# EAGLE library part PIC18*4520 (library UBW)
PIC18*4520 Microchip FLASH Microcontroller with A/D DEVICE FEATURES FeaturePIC18*4520 Program Memory (bytes) 32768 Program Memory (instructions) 16384 Interupt Sources 20 I/O Ports Ports A, B, C, D, E Capture/Compare/PWM Modules 1 Enhanced Capture/Compare/PWM Modules 1 Parallel Communications (PSP) Yes 10-bit Analog-to-Digital Module 13 input Channels Package Types 40-pin PDIP 44-pin TQFP 44-pin QFN NOTES: F only after 18, means standard voltage range from 4.2v to 5.5v LF after 18, means extended voltage range from 2.0v to 5.5v -E before / denotes extended temperature range from -40&deg;C to +120&deg;C -I before / denotes industrial temperature range from -40&deg;C to +85&deg;C /PT suffix denotes TQFP package /SO suffix denotes SOIC package /SP suffix denotes Skinny Plastic DIP package /P suffix denotes Plastic DIP package /ML suffix denotes QFN package
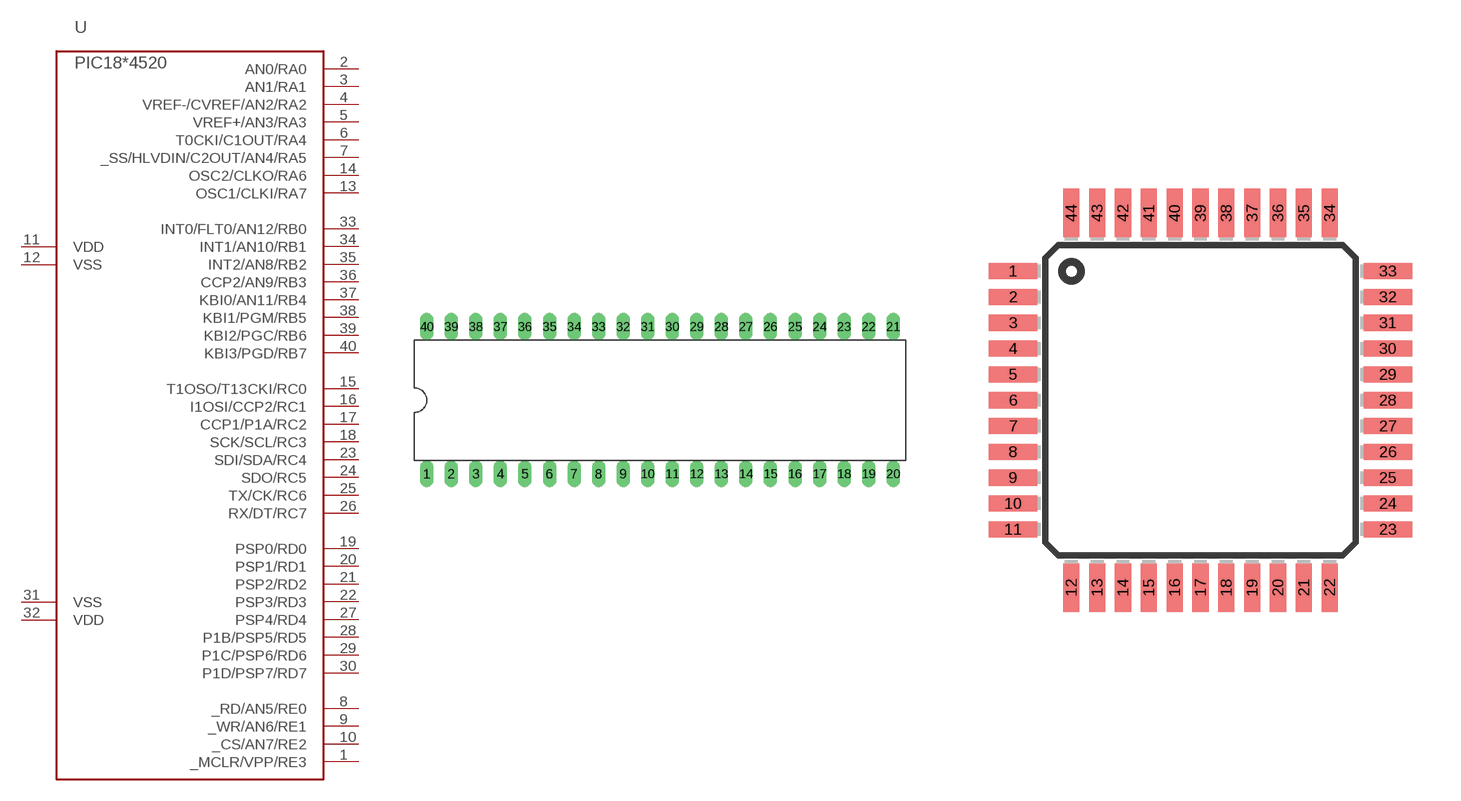
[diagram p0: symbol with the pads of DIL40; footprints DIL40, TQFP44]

Designator prefix -

## PIC18F4520-I/P, PIC18LF4520-I/P  [DIL40]
1  _MCLR/VPP/RE3  in
2  AN0/RA0
3  AN1/RA1
4  VREF-/CVREF/AN2/RA2
5  VREF+/AN3/RA3
6  T0CKI/C1OUT/RA4
7  _SS/HLVDIN/C2OUT/AN4/RA5
8  _RD/AN5/RE0
9  _WR/AN6/RE1
10  _CS/AN7/RE2
11  VDD  pwr
12  VSS  pwr
13  OSC1/CLKI/RA7
14  OSC2/CLKO/RA6
15  T1OSO/T13CKI/RC0
16  I1OSI/CCP2/RC1
17  CCP1/P1A/RC2
18  SCK/SCL/RC3
19  PSP0/RD0
20  PSP1/RD1
21  PSP2/RD2
22  PSP3/RD3
23  SDI/SDA/RC4
24  SDO/RC5
25  TX/CK/RC6
26  RX/DT/RC7
27  PSP4/RD4
28  P1B/PSP5/RD5
29  P1C/PSP6/RD6
30  P1D/PSP7/RD7
31  VSS  pwr
32  VDD  pwr
33  INT0/FLT0/AN12/RB0
34  INT1/AN10/RB1
35  INT2/AN8/RB2
36  CCP2/AN9/RB3
37  KBI0/AN11/RB4
38  KBI1/PGM/RB5
39  KBI2/PGC/RB6
40  KBI3/PGD/RB7

## PIC18F4520-E/P, PIC18LF4520-E/P  [DIL40]
Pads as for DIL40

## PIC18F4520-I/PT, PIC18LF4520-I/PT  [TQFP44]
1  RX/DT/RC7
2  PSP4/RD4
3  P1B/PSP5/RD5
4  P1C/PSP6/RD6
5  P1D/PSP7/RD7
6  VSS  pwr
7  VDD  pwr
8  INT0/FLT0/AN12/RB0
9  INT1/AN10/RB1
10  INT2/AN8/RB2
11  CCP2/AN9/RB3
14  KBI0/AN11/RB4
15  KBI1/PGM/RB5
16  KBI2/PGC/RB6
17  KBI3/PGD/RB7
18  _MCLR/VPP/RE3  in
19  AN0/RA0
20  AN1/RA1
21  VREF-/CVREF/AN2/RA2
22  VREF+/AN3/RA3
23  T0CKI/C1OUT/RA4
24  _SS/HLVDIN/C2OUT/AN4/RA5
25  _RD/AN5/RE0
26  _WR/AN6/RE1
27  _CS/AN7/RE2
28  VDD  pwr
29  VSS  pwr
30  OSC1/CLKI/RA7
31  OSC2/CLKO/RA6
32  T1OSO/T13CKI/RC0
35  I1OSI/CCP2/RC1
36  CCP1/P1A/RC2
37  SCK/SCL/RC3
38  PSP0/RD0
39  PSP1/RD1
40  PSP2/RD2
41  PSP3/RD3
42  SDI/SDA/RC4
43  SDO/RC5
44  TX/CK/RC6

## PIC18F4520-E/PT, PIC18LF4520-E/PT  [TQFP44]
Pads as for TQFP44

## Footprint DIL40 (pad centres in mm)
Dual In Line package type P
drill 0.9 long: 1 -24.13,-7.62; 2 -21.59,-7.62; 3 -19.05,-7.62; 4 -16.51,-7.62; 5 -13.97,-7.62; 6 -11.43,-7.62; 7 -8.89,-7.62; 8 -6.35,-7.62; 9 -3.81,-7.62; 10 -1.27,-7.62; 11 1.27,-7.62; 12 3.81,-7.62; 13 6.35,-7.62; 14 8.89,-7.62; 15 11.43,-7.62; 16 13.97,-7.62; 17 16.51,-7.62; 18 19.05,-7.62; 19 21.59,-7.62; 20 24.13,-7.62; 21 24.13,7.62; 22 21.59,7.62; 23 19.05,7.62; 24 16.51,7.62; 25 13.97,7.62; 26 11.43,7.62; 27 8.89,7.62; 28 6.35,7.62; 29 3.81,7.62; 30 1.27,7.62; 31 -1.27,7.62; 32 -3.81,7.62; 33 -6.35,7.62; 34 -8.89,7.62; 35 -11.43,7.62; 36 -13.97,7.62; 37 -16.51,7.62; 38 -19.05,7.62; 39 -21.59,7.62; 40 -24.13,7.62

## Footprint TQFP44 (pad centres in mm)
Thin Quad Flat Pack package type TQ
smd 1.5 x 0.5: 1 -5.8,4; 2 -5.8,3.2; 3 -5.8,2.4; 4 -5.8,1.6; 5 -5.8,0.8; 6 -5.8,0; 7 -5.8,-0.8; 8 -5.8,-1.6; 9 -5.8,-2.4; 10 -5.8,-3.2; 11 -5.8,-4; 23 5.8,-4; 24 5.8,-3.2; 25 5.8,-2.4; 26 5.8,-1.6; 27 5.8,-0.8; 28 5.8,0; 29 5.8,0.8; 30 5.8,1.6; 31 5.8,2.4; 32 5.8,3.2; 33 5.8,4
smd 0.5 x 1.5: 12 -4,-5.8; 13 -3.2,-5.8; 14 -2.4,-5.8; 15 -1.6,-5.8; 16 -0.8,-5.8; 17 0,-5.8; 18 0.8,-5.8; 19 1.6,-5.8; 20 2.4,-5.8; 21 3.2,-5.8; 22 4,-5.8; 34 4,5.8; 35 3.2,5.8; 36 2.4,5.8; 37 1.6,5.8; 38 0.8,5.8; 39 0,5.8; 40 -0.8,5.8; 41 -1.6,5.8; 42 -2.4,5.8; 43 -3.2,5.8; 44 -4,5.8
